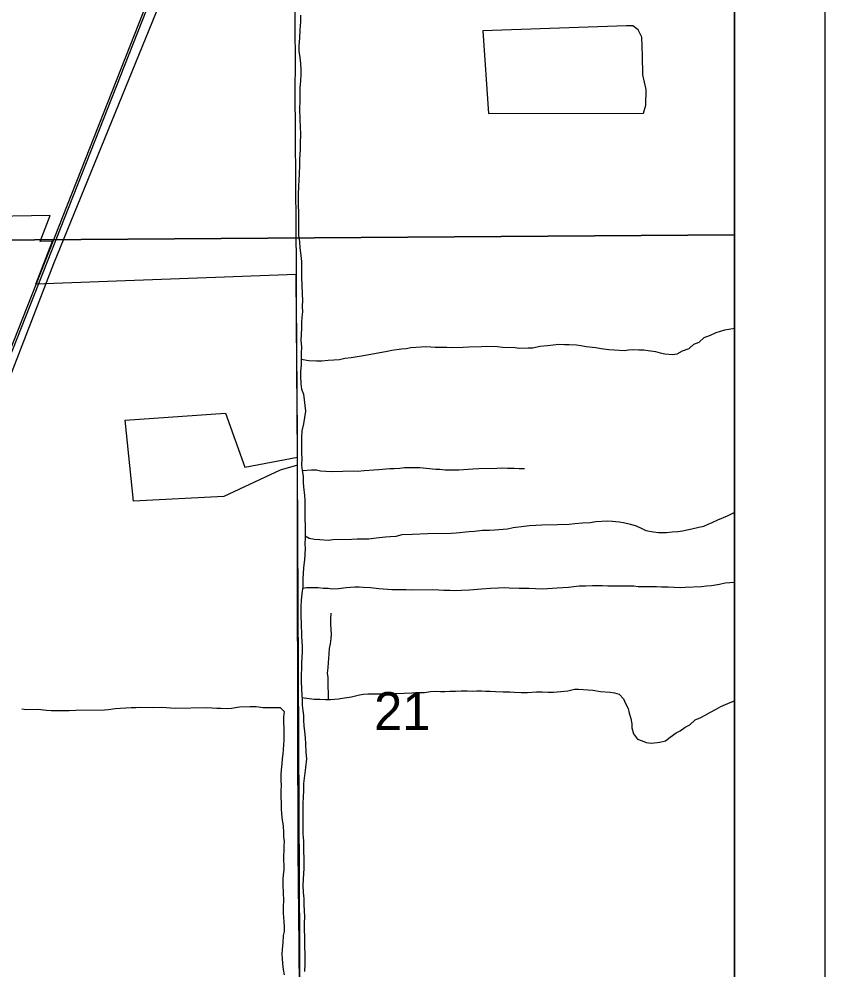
# Model space of a CAD drawing. Extents: x 0 to 34, y 0 to 22.
# Drawn here: x 8.111 to 9, y 17.466 to 18.515 of the extents above; entities that cross this region are included whole.
import ezdxf

# ---------------------------------------------------------------- set-up
doc = ezdxf.new("R2010")
doc.units = 0
for name, color, linetype in [('GM_X_County_Road', 7, 'Continuous'), ('GM_X_Minor_Lake', 7, 'Continuous'), ('GM_X_Minor_River', 7, 'Continuous'), ('GM_X_Rail_Line', 7, 'Continuous'), ('GM_X_Section_Text', 7, 'Continuous'), ('GM_X_State_Route', 7, 'Continuous'), ('GM_X_Township_Road', 7, 'Continuous'), ('GM_X_Unincorporated', 7, 'Continuous'), ('SH_Data', 7, 'Continuous')]:
    doc.layers.add(name, color=color, linetype=linetype)

msp = doc.modelspace()

# ---------------------------------------------------------------- linework, layer by layer
at = {"layer": 'GM_X_County_Road'}
msp.add_line((8.4183, 18.0224), (8.4183, 18.0314), dxfattribs=at)
for points in [[(8.417, 18.2326), (8.4165, 18.293), (8.4164, 18.3271), (8.4158, 18.3953), (8.4156, 18.4294), (8.4158, 18.4727), (8.4157, 18.5006), (8.4155, 18.5223), (8.4159, 18.5409), (8.416, 18.5966), (8.4154, 18.6524), (8.4155, 18.702), (8.4154, 18.7391), (8.4153, 18.7716)], [(8.4183, 18.0314), (8.418, 18.058), (8.4176, 18.0986), (8.4173, 18.1548), (8.4172, 18.2048), (8.417, 18.2326)], [(8.422, 17.2631), (8.4219, 17.297), (8.421, 17.3841), (8.4204, 17.4431), (8.4199, 17.4929), (8.4195, 17.5271), (8.4189, 17.5986), (8.4188, 17.6483), (8.4186, 17.6918), (8.4186, 17.7758), (8.4183, 17.8815), (8.4181, 17.9281), (8.4183, 17.9746), (8.4181, 17.9932), (8.4183, 18.0224)]]:
    msp.add_lwpolyline(points, dxfattribs=at)
at = {"layer": 'GM_X_Minor_Lake'}
for points in [[(8.629, 18.4108), (8.7998, 18.411), (8.8024, 18.4201), (8.8026, 18.4371), (8.7991, 18.4534), (8.7986, 18.4743), (8.7981, 18.4948), (8.7938, 18.5031), (8.7881, 18.5072), (8.7809, 18.5075), (8.6227, 18.5018)], [(8.6227, 18.5018), (8.629, 18.4108)]]:
    msp.add_lwpolyline(points, dxfattribs=at)
at = {"layer": 'GM_X_Minor_River'}
for points in [[(8.4215, 18.519), (8.4216, 18.5118), (8.4209, 18.5031), (8.4203, 18.4939), (8.4196, 18.4856), (8.4197, 18.4795), (8.4206, 18.4723), (8.4214, 18.4658), (8.4219, 18.459), (8.422, 18.4541), (8.4213, 18.4469), (8.4206, 18.4389), (8.4208, 18.4241), (8.4205, 18.4165), (8.4207, 18.4035), (8.4212, 18.3967), (8.4213, 18.3872), (8.421, 18.3789), (8.4211, 18.3709), (8.4205, 18.3602), (8.4202, 18.3545), (8.42, 18.3431), (8.4197, 18.3382), (8.4194, 18.3295), (8.4187, 18.3226), (8.4192, 18.2884), (8.4193, 18.2763), (8.4202, 18.2694), (8.4206, 18.2626), (8.4219, 18.2543), (8.4224, 18.2474), (8.4226, 18.2285), (8.4231, 18.2231), (8.4232, 18.211), (8.4237, 18.2053), (8.4234, 18.1977), (8.4235, 18.192), (8.4228, 18.1863), (8.4225, 18.1802), (8.4226, 18.1738), (8.4223, 18.1673), (8.422, 18.1604), (8.4224, 18.1536), (8.4222, 18.146), (8.4223, 18.1331), (8.4216, 18.1263), (8.4213, 18.1213), (8.4218, 18.1126), (8.4227, 18.1069), (8.4246, 18.1012), (8.4255, 18.0952), (8.4263, 18.0887), (8.4268, 18.0826), (8.4247, 18.0686), (8.4229, 18.0609), (8.4226, 18.0537), (8.4227, 18.0438), (8.4224, 18.0355), (8.4229, 18.0306), (8.4226, 18.0229), (8.4234, 18.0173), (8.4243, 18.0108), (8.4244, 18.004), (8.4248, 17.999), (8.4257, 17.9896), (8.4261, 17.9846)], [(8.4222, 18.1399), (8.4306, 18.1385), (8.439, 18.1379), (8.4451, 18.138), (8.4519, 18.1388), (8.4645, 18.1397), (8.4705, 18.141), (8.4774, 18.1418), (8.4819, 18.1426), (8.491, 18.1439), (8.4967, 18.1451), (8.5111, 18.1476), (8.5172, 18.1488), (8.5221, 18.15), (8.5328, 18.1513), (8.5381, 18.1517), (8.543, 18.1526), (8.5544, 18.1535), (8.5597, 18.1539), (8.5654, 18.1536), (8.57, 18.1533), (8.5829, 18.1531), (8.5883, 18.1528), (8.6008, 18.153), (8.6073, 18.1534), (8.621, 18.154), (8.6263, 18.1541), (8.6388, 18.1538), (8.6442, 18.1531), (8.6583, 18.1526), (8.6628, 18.1519), (8.6727, 18.1524), (8.6777, 18.1525), (8.6856, 18.1541), (8.694, 18.155), (8.7001, 18.1558), (8.7065, 18.1563), (8.7126, 18.156), (8.7179, 18.156), (8.7259, 18.1558), (8.7305, 18.1551), (8.7366, 18.154), (8.7473, 18.1526), (8.753, 18.1516), (8.7617, 18.1505), (8.7674, 18.1502), (8.7789, 18.1496), (8.7834, 18.1501), (8.7891, 18.1505), (8.7948, 18.1502), (8.8002, 18.1503), (8.8051, 18.1496), (8.8131, 18.1482), (8.8181, 18.1467), (8.8234, 18.1457), (8.8318, 18.145), (8.8371, 18.1458), (8.8428, 18.149), (8.8503, 18.1517), (8.8552, 18.1563), (8.8613, 18.1587), (8.8669, 18.1637), (8.8737, 18.1665), (8.8798, 18.1692), (8.8896, 18.1724), (8.8961, 18.1732), (8.9, 18.174)], [(8.4235, 18.017), (8.4337, 18.0178), (8.439, 18.0178), (8.4436, 18.0168), (8.4493, 18.0165), (8.4565, 18.0162), (8.468, 18.0163), (8.4801, 18.0169), (8.4847, 18.0166), (8.4915, 18.017), (8.5025, 18.0179), (8.5079, 18.0184), (8.52, 18.0193), (8.5246, 18.0194), (8.531, 18.0198), (8.536, 18.0203), (8.5531, 18.0205), (8.5706, 18.0188), (8.5752, 18.0185), (8.5809, 18.0178), (8.5961, 18.018), (8.6117, 18.019), (8.6182, 18.0195), (8.6379, 18.0197), (8.644, 18.0202), (8.6497, 18.0199), (8.6573, 18.0196), (8.6627, 18.0193), (8.6684, 18.0194)], [(8.4261, 17.9846), (8.4262, 17.9774), (8.4267, 17.9425), (8.4264, 17.9364), (8.4265, 17.9311), (8.4262, 17.925), (8.4259, 17.9185), (8.4248, 17.9102), (8.4245, 17.9033), (8.4242, 17.8984), (8.424, 17.8889), (8.4229, 17.8816), (8.4223, 17.8737), (8.422, 17.8672), (8.4217, 17.8619), (8.4217, 17.8558), (8.4222, 17.8497), (8.4224, 17.8342), (8.4229, 17.8285), (8.4233, 17.8232), (8.4234, 17.8167), (8.4231, 17.8114), (8.4224, 17.8045), (8.4225, 17.7992), (8.4222, 17.792), (8.4223, 17.784), (8.4224, 17.7764), (8.4229, 17.7696), (8.4233, 17.7643), (8.4234, 17.7586), (8.4242, 17.7525), (8.4247, 17.7472), (8.4247, 17.7415), (8.4252, 17.7358), (8.4257, 17.7294), (8.4265, 17.7225), (8.427, 17.7157), (8.4275, 17.7062), (8.428, 17.6994), (8.4269, 17.6899), (8.4256, 17.6781), (8.4249, 17.672), (8.4246, 17.6648), (8.4243, 17.6572), (8.424, 17.6503), (8.4242, 17.6378), (8.4239, 17.6306), (8.4241, 17.6161), (8.4246, 17.6089), (8.425, 17.5782), (8.4243, 17.5668), (8.4241, 17.5592), (8.4245, 17.5523), (8.425, 17.5451), (8.4251, 17.5379), (8.4256, 17.5326), (8.4257, 17.5246), (8.4254, 17.5185), (8.4255, 17.5106), (8.4259, 17.503), (8.4263, 17.4733), (8.4257, 17.465)], [(8.4267, 17.9451), (8.4309, 17.9425), (8.437, 17.9415), (8.4427, 17.9412), (8.4518, 17.9405), (8.4571, 17.941), (8.4781, 17.9413), (8.4841, 17.9417), (8.4967, 17.9419), (8.505, 17.9428), (8.5153, 17.944), (8.5202, 17.9445), (8.5271, 17.9449), (8.5335, 17.9466), (8.5449, 17.9471), (8.5617, 17.9477), (8.5875, 17.948), (8.5932, 17.9485), (8.6076, 17.9498), (8.6133, 17.9503), (8.6221, 17.9512), (8.6301, 17.9513), (8.6354, 17.9517), (8.6498, 17.953), (8.6559, 17.9543), (8.668, 17.9556), (8.6741, 17.9564), (8.681, 17.9569), (8.6878, 17.9573), (8.7049, 17.9576), (8.7178, 17.9581), (8.7239, 17.9586), (8.7327, 17.9595), (8.741, 17.9599), (8.7471, 17.9608), (8.76, 17.9617), (8.7657, 17.9614), (8.773, 17.9604), (8.7779, 17.9597), (8.7855, 17.9579), (8.7917, 17.9561), (8.7974, 17.9535), (8.8024, 17.9509), (8.8108, 17.9495), (8.8165, 17.9488), (8.8252, 17.9489), (8.8313, 17.9494), (8.8378, 17.9498), (8.8427, 17.9507), (8.8533, 17.9527), (8.8609, 17.9547), (8.8662, 17.9559), (8.8711, 17.9579), (8.8757, 17.9598), (8.8817, 17.9626), (8.8923, 17.9673), (8.8991, 17.9704), (8.9, 17.9709)], [(8.4238, 17.8874), (8.4282, 17.8882), (8.4331, 17.8882), (8.4411, 17.888), (8.4464, 17.8873), (8.4518, 17.8873), (8.4563, 17.8866), (8.4635, 17.8871), (8.4719, 17.888), (8.4765, 17.8884), (8.4814, 17.8889), (8.486, 17.8889), (8.4905, 17.8886), (8.4985, 17.888), (8.508, 17.887), (8.5221, 17.886), (8.5316, 17.8858), (8.5381, 17.8858), (8.5438, 17.8855), (8.567, 17.8858), (8.5739, 17.8856), (8.5796, 17.8852), (8.586, 17.8853), (8.5918, 17.885), (8.599, 17.8851), (8.6077, 17.8856), (8.621, 17.8866), (8.6309, 17.8875), (8.6396, 17.8879), (8.6469, 17.888), (8.6518, 17.8877), (8.6628, 17.8875), (8.6682, 17.8876), (8.6735, 17.8873), (8.6807, 17.887), (8.6887, 17.8867), (8.7047, 17.8877), (8.7172, 17.8886), (8.729, 17.8899), (8.7358, 17.89), (8.7434, 17.8905), (8.7545, 17.8902), (8.7606, 17.8899), (8.7739, 17.8901), (8.7891, 17.8899), (8.794, 17.8892), (8.7997, 17.8893), (8.8142, 17.8891), (8.8195, 17.8888), (8.8271, 17.8889), (8.8401, 17.8883), (8.8458, 17.8884), (8.8636, 17.8894), (8.8693, 17.8899), (8.8747, 17.8903), (8.8838, 17.892), (8.8898, 17.8932), (8.9, 17.8942)], [(8.4522, 17.7647), (8.4525, 17.773), (8.452, 17.7776), (8.4519, 17.789), (8.4514, 17.7939), (8.4518, 17.7996), (8.4524, 17.8053), (8.4528, 17.8099), (8.4531, 17.8152), (8.4534, 17.8209), (8.4545, 17.8262), (8.4551, 17.8319), (8.4555, 17.8369), (8.4554, 17.8422), (8.4549, 17.8479), (8.4549, 17.8528), (8.4552, 17.8597)], [(8.4231, 17.7668), (8.4366, 17.7652), (8.4427, 17.7649), (8.4492, 17.7646), (8.4545, 17.7647), (8.4632, 17.7656), (8.4701, 17.7664), (8.4777, 17.7677), (8.4864, 17.7697), (8.4909, 17.7705), (8.4959, 17.7709), (8.5092, 17.7711), (8.5172, 17.7708), (8.5248, 17.7713), (8.5358, 17.7715), (8.5442, 17.772), (8.5514, 17.7724), (8.5582, 17.7725), (8.5647, 17.7734), (8.57, 17.7738), (8.5757, 17.7735), (8.5806, 17.7736), (8.5863, 17.774), (8.5924, 17.7737), (8.5985, 17.7742), (8.6054, 17.7743), (8.6111, 17.774), (8.616, 17.7741), (8.621, 17.7741), (8.6255, 17.7738), (8.6305, 17.7739), (8.6366, 17.7736), (8.6449, 17.7733), (8.6525, 17.773), (8.6571, 17.7727), (8.6647, 17.7724), (8.6719, 17.7725), (8.6818, 17.773), (8.6879, 17.7731), (8.6948, 17.7728), (8.7005, 17.7729), (8.7088, 17.7734), (8.7164, 17.7743), (8.7236, 17.7759), (8.7282, 17.7759), (8.7388, 17.7753), (8.7438, 17.775), (8.7522, 17.7736), (8.7632, 17.7726), (8.7678, 17.7719), (8.7728, 17.7704), (8.7778, 17.7656), (8.7801, 17.7603), (8.7829, 17.7546), (8.7841, 17.7497), (8.786, 17.7436), (8.7869, 17.738), (8.7869, 17.7334), (8.7889, 17.727), (8.7932, 17.7209), (8.7982, 17.7191), (8.8027, 17.7173), (8.8088, 17.7166), (8.8179, 17.7175), (8.824, 17.7191), (8.8293, 17.7233), (8.8357, 17.728), (8.8402, 17.7303), (8.8459, 17.7342), (8.8508, 17.7369), (8.8568, 17.7423), (8.8629, 17.745), (8.8678, 17.7474), (8.8738, 17.7509), (8.8799, 17.754), (8.8851, 17.7571), (8.8901, 17.7591), (8.8954, 17.7614), (8.9, 17.7632)], [(8.1142, 17.7545), (8.1192, 17.7538), (8.1317, 17.7539), (8.1412, 17.7529), (8.1466, 17.7526), (8.1664, 17.7525), (8.1736, 17.753), (8.2051, 17.7534), (8.2097, 17.7538), (8.2169, 17.7547), (8.2348, 17.7557), (8.2397, 17.7558), (8.2454, 17.7562), (8.2583, 17.756), (8.2682, 17.7561), (8.2831, 17.7552), (8.3181, 17.7557), (8.3291, 17.755), (8.3337, 17.7551), (8.3409, 17.7548), (8.3455, 17.7553), (8.3542, 17.7565), (8.366, 17.7571), (8.3724, 17.7568), (8.3804, 17.7557), (8.3991, 17.756), (8.4033, 17.7515), (8.4026, 17.7454), (8.4027, 17.7404), (8.4032, 17.7321), (8.4029, 17.7241), (8.403, 17.7196), (8.4026, 17.715), (8.4023, 17.7093), (8.402, 17.7047), (8.4013, 17.6994), (8.401, 17.6937), (8.4003, 17.6872), (8.3997, 17.6815), (8.3997, 17.6751), (8.4002, 17.6701), (8.3999, 17.6637), (8.4001, 17.6443), (8.4006, 17.6386), (8.4011, 17.6318), (8.4023, 17.6253), (8.4028, 17.6181), (8.4028, 17.6132), (8.4033, 17.6083), (8.403, 17.6037), (8.403, 17.598), (8.4027, 17.5927), (8.4029, 17.5764), (8.4022, 17.5714), (8.4019, 17.5665), (8.402, 17.5611), (8.4025, 17.5509), (8.4026, 17.5441), (8.4023, 17.5353), (8.4024, 17.5292), (8.4028, 17.5247), (8.4029, 17.5194), (8.4034, 17.5141), (8.4034, 17.5091), (8.4023, 17.5046), (8.4021, 17.4966), (8.4014, 17.4893), (8.4007, 17.4836), (8.4011, 17.4791), (8.4016, 17.4738), (8.4024, 17.4669), (8.4033, 17.4613)]]:
    msp.add_lwpolyline(points, dxfattribs=at)
at = {"layer": 'GM_X_Rail_Line'}
for points in [[(7.8864, 17.5993), (7.909, 17.6604), (8.002, 17.8987), (8.2924, 18.6349), (8.4135, 18.9454), (8.4555, 19.0533), (8.5344, 19.2547), (8.5895, 19.3952), (8.6143, 19.4599), (8.6342, 19.5105), (8.6459, 19.5388), (8.6586, 19.5643), (8.6731, 19.5919), (8.6878, 19.6183), (8.6998, 19.6402), (8.7381, 19.7096), (8.7826, 19.7894), (8.8238, 19.8634), (8.8505, 19.9123), (8.8668, 19.9463), (8.881, 19.9792), (8.9, 20.0244)], [(7.7573, 17.2724), (7.8518, 17.515), (7.9112, 17.6595), (8.0042, 17.8978), (8.2946, 18.6341), (8.4157, 18.9445), (8.4577, 19.0524), (8.5366, 19.2539), (8.5917, 19.3944), (8.6165, 19.4591), (8.6364, 19.5096), (8.6481, 19.5379), (8.6607, 19.5632), (8.6752, 19.5908), (8.6898, 19.6172), (8.7019, 19.6391), (8.7402, 19.7084), (8.7847, 19.7883), (8.8259, 19.8623), (8.8526, 19.9112), (8.869, 19.9454), (8.8831, 19.9783), (8.9, 20.0183)], [(6.4606, 14.1), (6.4571, 14.1954), (6.4477, 14.4405), (6.4524, 14.5081), (6.4637, 14.5568), (6.4857, 14.6083), (6.5473, 14.6979), (6.8861, 15.1309), (7.2406, 15.5724), (7.3338, 15.6825), (7.3851, 15.7562), (7.4225, 15.8224), (7.4495, 15.9132), (7.4686, 16.0084), (7.5816, 16.5648), (7.6436, 16.8869), (7.6684, 17.0095), (7.6975, 17.0913), (7.758, 17.2454), (8.0083, 17.8807), (8.1494, 18.2455), (8.2773, 18.5592), (8.2934, 18.6184), (8.454, 19.2815)]]:
    msp.add_lwpolyline(points, dxfattribs=at)
at = {"layer": 'GM_X_State_Route'}
msp.add_lwpolyline([(8.4218, 17.2637), (8.418, 18.023), (8.3991, 18.0174), (8.3368, 17.9884), (8.2372, 17.9832), (8.2279, 18.0725), (8.3386, 18.0802), (8.3602, 18.0209), (8.418, 18.0319), (8.4168, 18.2332), (8.1295, 18.2225), (8.1478, 18.27), (8.1343, 18.2698), (8.1453, 18.2982), (7.9384, 18.2947)], dxfattribs=at)
at = {"layer": 'GM_X_Township_Road'}
msp.add_lwpolyline([(8.9, 17.2634), (8.9, 20.9), (5.7818, 20.9)], dxfattribs=at)
at = {"layer": 'GM_X_Unincorporated'}
for points in [[(8.9, 18.2769), (8.9, 19.2757), (7.9079, 19.2721), (7.9217, 18.2701)], [(8.9, 17.263), (8.9, 18.2769), (7.9217, 18.2701), (7.9201, 17.2543)]]:
    msp.add_lwpolyline(points, close=True, dxfattribs=at)
at = {"layer": 'SH_Data'}
for p, q in [((9, 21), (9, 14)), ((8.9, 20.9), (8.9, 14.1))]:
    msp.add_line(p, q, dxfattribs=at)

# ---------------------------------------------------------------- texts
at = {"layer": 'GM_X_Section_Text'}
msp.add_text('21', height=0.04186, rotation=0, dxfattribs=at).set_placement((8.5026, 17.731))

doc.saveas('drawing.dxf')
